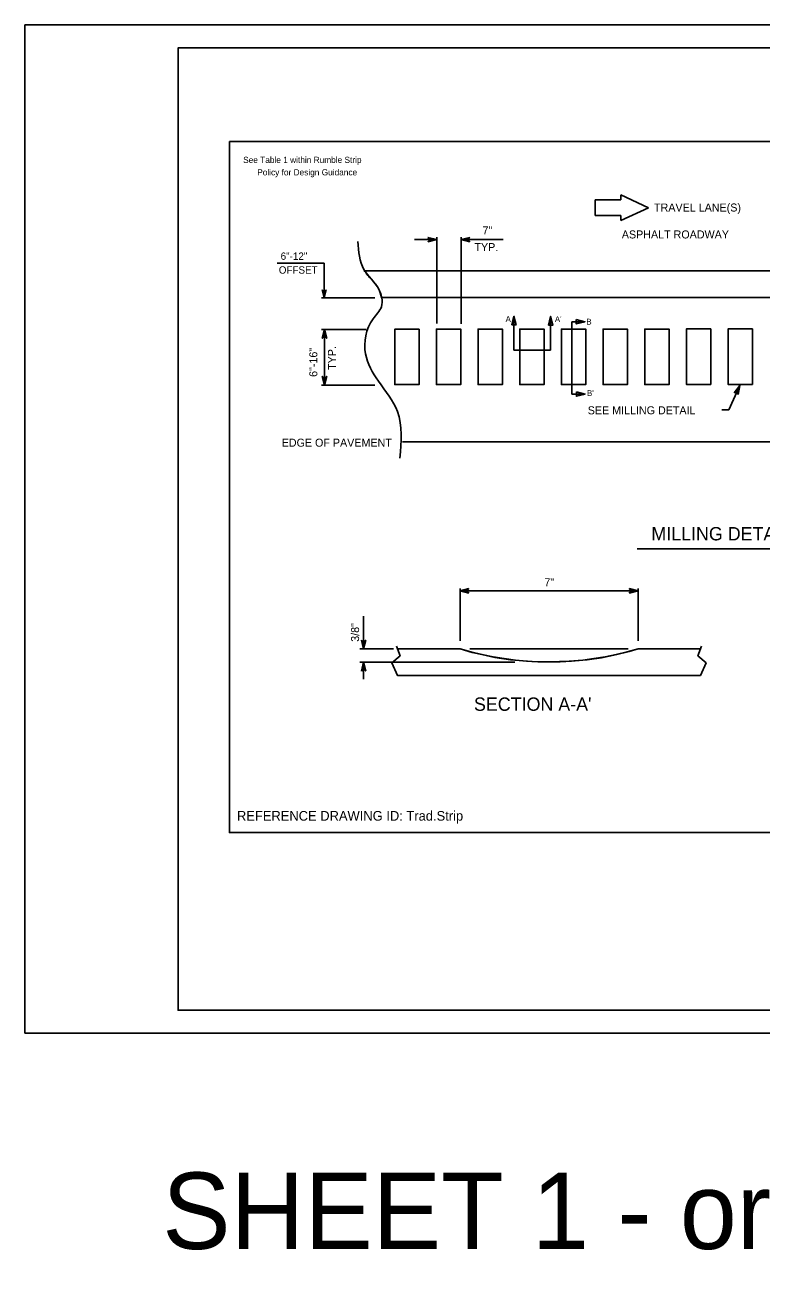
# Model space of a CAD drawing. Extents: x 1994737 to 2001433, y 527447 to 529360.
# Drawn here: x 1994737 to 1995696, y 527488 to 529114 of the extents above; entities that cross this region are included whole.
import ezdxf

# ---------------------------------------------------------------- set-up
doc = ezdxf.new("R2010")
doc.units = 0
for name, color, linetype in [('Default', 7, 'Continuous'), ('GSBWFILL', 7, 'Continuous'), ('Old_Level_33', 7, 'Continuous'), ('Prop Sign E Yield Sign Ahead CELL', 7, 'Continuous'), ('Prop Support Two', 7, 'Continuous')]:
    doc.layers.add(name, color=color, linetype=linetype)

# ---------------------------------------------------------------- blocks, each defined once
blk = doc.blocks.new('DTF')
at = {"layer": 'Default'}
for p, q in [((-10.33475, 4.8755), (-10.33625, 2.90475)), ((0, 0), (-10.33475, 4.8755)), ((-19.936, 2.9115), (-19.9395, -2.8845)), ((-10.33625, 2.90475), (-19.936, 2.9115)), ((-10.34125, -4.8615), (0, 0)), ((-19.9395, -2.8845), (-10.3405, -2.891)), ((-10.3405, -2.891), (-10.34125, -4.8615))]:
    blk.add_line(p, q, dxfattribs=at)
blk = doc.blocks.new('TERM2')
at = {"layer": 'Default'}
for p, q in [((-6.25, 1.563), (0, 0)), ((-4.687, 0), (-6.25, 1.563)), ((0, 0), (-6.25, -1.563)), ((-6.25, -1.563), (-4.687, 0))]:
    blk.add_line(p, q, dxfattribs=at)

msp = doc.modelspace()

# ---------------------------------------------------------------- linework, layer by layer
at = {"layer": 'Default'}
for p, q in [((1995273.6, 528834.2), (1995244.7, 528834.2)), ((1995273.6, 528724.6), (1995273.6, 528837.5)), ((1995305.3, 528724.5), (1995305.3, 528837.5)), ((1995305.3, 528834.2), (1995360.2, 528834.2)), ((1995065.8, 528803.5), (1995127, 528803.5)), ((1995127, 528758.1), (1995127, 528803.5)), ((1995178.8, 528793.5), (1995986.2, 528793.5)), ((1995985.9, 528793.5), (1995179.6, 528793.5)), ((1995193, 528758.1), (1995123.4, 528758.1)), ((1995201.2, 528758.5), (1995964.5, 528758.5)), ((1995201.7, 528758.5), (1995963.8, 528758.5)), ((1995374.1, 528689.9), (1995374.1, 528734.3)), ((1995422, 528689.9), (1995422, 528734.1)), ((1995449.4, 528727.1), (1995449.4, 528632.7)), ((1995449.6, 528727.1), (1995466, 528727.1)), ((1995181.6, 528717), (1995123.3, 528717)), ((1995127.3, 528717), (1995127.3, 528644.6)), ((1995374.1, 528689.9), (1995422, 528689.9)), ((1995193, 528644.6), (1995123.3, 528644.6)), ((1995668.3, 528643.9), (1995654, 528612.1)), ((1995449.4, 528632.7), (1995466.1, 528632.7)), ((1995654.1, 528612.1), (1995645.2, 528612.1)), ((1995228.8, 528570.4), (1995936.7, 528570.4)), ((1995534.7, 528431.2), (1995796.9, 528431.2)), ((1995303.9, 528311.1), (1995303.9, 528379.5)), ((1995535.8, 528311.1), (1995535.8, 528379.5)), ((1995303.9, 528376.3), (1995535.8, 528376.3)), ((1995178.3, 528300.5), (1995178.3, 528343.3)), ((1995217.4, 528300.5), (1995173.2, 528300.5)), ((1995221.2, 528304), (1995225.8, 528291.6)), ((1995222.5, 528300.5), (1995303.9, 528300.5)), ((1995316.7, 528300.5), (1995523, 528300.5)), ((1995535.8, 528300.5), (1995617.2, 528300.5)), ((1995618.5, 528304), (1995613.9, 528291.6)), ((1995375.5, 528283.1), (1995173.2, 528283.1)), ((1995178.3, 528283.1), (1995178.3, 528261.1)), ((1995225.8, 528291.6), (1995215.2, 528282.3)), ((1995215.2, 528282.3), (1995222.5, 528265.7)), ((1995613.9, 528291.6), (1995624.5, 528282.3)), ((1995624.5, 528282.3), (1995617.2, 528265.7)), ((1995222.5, 528265.7), (1995617.2, 528265.7))]:
    msp.add_line(p, q, dxfattribs=at)
for points in [[(1995003.5, 528962), (1996421.2, 528962), (1996421.2, 528061), (1995003.5, 528061)], [(1995371.3, 528722.9), (1995374.1, 528734.3), (1995377, 528722.9)], [(1995419.2, 528722.7), (1995422, 528734.1), (1995424.9, 528722.7)], [(1995455.3, 528729.9), (1995466.7, 528727.1), (1995455.3, 528724.2)], [(1995218.9, 528717.4), (1995250.6, 528717.4), (1995250.6, 528645.1), (1995218.9, 528645.1)], [(1995250.6, 528645.1), (1995218.9, 528645.1), (1995218.9, 528717.4), (1995250.6, 528717.4)], [(1995273.2, 528717.6), (1995304.9, 528717.6), (1995304.9, 528645.2), (1995273.2, 528645.2)], [(1995273.2, 528717.6), (1995304.9, 528717.6), (1995304.9, 528645.2), (1995273.2, 528645.2)], [(1995327.5, 528717.6), (1995359.2, 528717.6), (1995359.2, 528645.2), (1995327.5, 528645.2)], [(1995327.5, 528645.2), (1995359.2, 528645.2), (1995359.2, 528717.6), (1995327.5, 528717.6)], [(1995381.8, 528717.6), (1995413.5, 528717.6), (1995413.5, 528645.2), (1995381.8, 528645.2)], [(1995381.8, 528717.6), (1995413.5, 528717.6), (1995413.5, 528645.2), (1995381.8, 528645.2)], [(1995436, 528717.5), (1995467.7, 528717.5), (1995467.7, 528645.1), (1995436, 528645.1)], [(1995436, 528645.1), (1995467.7, 528645.1), (1995467.7, 528717.5), (1995436, 528717.5)], [(1995490.3, 528717.5), (1995521.9, 528717.5), (1995521.9, 528645.1), (1995490.3, 528645.1)], [(1995490.3, 528717.5), (1995521.9, 528717.5), (1995521.9, 528645.1), (1995490.3, 528645.1)], [(1995544.6, 528717.5), (1995576.2, 528717.5), (1995576.2, 528645.1), (1995544.6, 528645.1)], [(1995544.6, 528717.5), (1995576.2, 528717.5), (1995576.2, 528645.1), (1995544.6, 528645.1)], [(1995598.9, 528717.7), (1995630.5, 528717.7), (1995630.5, 528645.3), (1995598.9, 528645.3)], [(1995598.9, 528717.7), (1995630.5, 528717.7), (1995630.5, 528645.3), (1995598.9, 528645.3)], [(1995653.1, 528717.7), (1995684.8, 528717.7), (1995684.8, 528645.3), (1995653.1, 528645.3)], [(1995653.1, 528717.7), (1995684.8, 528717.7), (1995684.8, 528645.3), (1995653.1, 528645.3)], [(1995455.5, 528635.6), (1995466.9, 528632.7), (1995455.5, 528629.9)], [(1995535.8, 528300.5), (1995617.2, 528300.5), (1995613.9, 528291.6), (1995624.5, 528282.3), (1995617.2, 528265.7), (1995222.5, 528265.7), (1995215.2, 528282.3), (1995225.8, 528291.6), (1995222.5, 528300.5), (1995303.9, 528300.5), (1995319.6, 528296), (1995332.5, 528293.4), (1995349.3, 528289.5), (1995369.6, 528286.5), (1995397.6, 528283.9), (1995420.4, 528283.5), (1995446.3, 528284.4), (1995469.6, 528286.5), (1995488.1, 528289.1), (1995508.3, 528293.4), (1995524.3, 528297.3), (1995535.8, 528300.5)]]:
    msp.add_lwpolyline(points, close=True, dxfattribs=at)
for points in [[(1995218.9, 528645.1), (1995250.6, 528645.1), (1995250.6, 528717.4), (1995218.9, 528717.4), (1995218.9, 528645.1)], [(1995273.2, 528645.2), (1995304.9, 528645.2), (1995304.9, 528717.6), (1995273.2, 528717.6), (1995273.2, 528645.2)], [(1995327.5, 528645.2), (1995359.2, 528645.2), (1995359.2, 528717.6), (1995327.5, 528717.6), (1995327.5, 528645.2)], [(1995381.8, 528645.2), (1995413.5, 528645.2), (1995413.5, 528717.6), (1995381.8, 528717.6), (1995381.8, 528645.2)], [(1995436, 528645.1), (1995467.7, 528645.1), (1995467.7, 528717.5), (1995436, 528717.5), (1995436, 528645.1)], [(1995490.3, 528645.1), (1995521.9, 528645.1), (1995521.9, 528717.5), (1995490.3, 528717.5), (1995490.3, 528645.1)], [(1995544.6, 528645.1), (1995576.2, 528645.1), (1995576.2, 528717.5), (1995544.6, 528717.5), (1995544.6, 528645.1)], [(1995598.9, 528645.3), (1995630.5, 528645.3), (1995630.5, 528717.7), (1995598.9, 528717.7), (1995598.9, 528645.3)], [(1995653.1, 528645.3), (1995684.8, 528645.3), (1995684.8, 528717.7), (1995653.1, 528717.7), (1995653.1, 528645.3)]]:
    msp.add_lwpolyline(points, dxfattribs=at)
msp.add_arc((1995419.9, 528689.6), 406, 253.4, 286.5999, dxfattribs=at)
for points in [[(1995170.8, 528831.7), (1995178.8, 528795.2), (1995197.6, 528770.4), (1995201.5, 528746.6), (1995190.7, 528730.8), (1995180.8, 528685.2), (1995197.6, 528649.6), (1995222.3, 528609.9), (1995225.5, 528549.4)], [(1995179.6, 528793.5), (1995181.6, 528790.4), (1995183.8, 528787.4), (1995188.7, 528782), (1995193.6, 528776.5), (1995195.7, 528773.6), (1995197.6, 528770.4), (1995201.7, 528758.5)]]:
    msp.add_spline(points, degree=3, dxfattribs=at)
at = {"layer": 'GSBWFILL'}
for p, q in [((1996749.7, 529114.1), (1994737.1, 529114.1)), ((1994737.1, 529114.1), (1994737.1, 527799.4)), ((1994737.1, 527799.4), (1996749.7, 527799.4))]:
    msp.add_line(p, q, dxfattribs=at)
at = {"layer": 'Old_Level_33'}
msp.add_line((1994937.9, 529084.2), (1994937.9, 529084.2), dxfattribs=at)
at = {"layer": 'Prop Sign E Yield Sign Ahead CELL'}
msp.add_lwpolyline([(1996729.4, 529084.2), (1994936.7, 529084.2), (1994936.7, 527829.3), (1996729.4, 527829.3)], close=True, dxfattribs=at)
at = {"layer": 'Prop Support Two'}
msp.add_line((1994737.1, 527799.4), (1994737.1, 527799.4), dxfattribs=at)

# ---------------------------------------------------------------- block references
at = {"layer": 'Default', "xscale": 3.4793784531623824, "yscale": 3.4793784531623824}
msp.add_blockref('DTF', (1995549.3, 528875.8), dxfattribs=at)
at = {"layer": 'Default'}
for p, xscale, yscale, rotation in [((1995273.6, 528834.2), 1.8556685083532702, 1.8556685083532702, 2.7372046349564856e-11), ((1995305.3, 528834.2), 1.8556685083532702, 1.8556685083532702, -179.99999999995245), ((1995127, 528758.1), 1.7040114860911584, 1.7040114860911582, -89.99999999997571), ((1995127.3, 528717), 1.8556685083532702, 1.8556685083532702, 89.99999999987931), ((1995127.3, 528644.6), 1.8556685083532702, 1.8556685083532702, -90.0000000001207), ((1995668.3, 528643.9), 1.8556685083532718, 1.8556685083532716, 65.81937702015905), ((1995303.9, 528376.3), 1.8556685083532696, 1.85566850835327, 179.99984077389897), ((1995535.8, 528376.3), 1.8556685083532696, 1.85566850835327, -0.0001592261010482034), ((1995178.3, 528300.5), 1.855668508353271, 1.8556685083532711, -89.99968490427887), ((1995178.3, 528283.1), 1.8556685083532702, 1.8556685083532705, 89.99993359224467)]:
    msp.add_blockref('TERM2', p, dxfattribs=dict(at, xscale=xscale, yscale=yscale, rotation=rotation))

# ---------------------------------------------------------------- texts
for s, height, rotation, p in [('See Table 1 within Rumble Strip', 8.074, 360, (1995021.4, 528934.1)), ('Policy for Design Guidance', 8.074, 360, (1995039.7, 528917.9)), ('TRAVEL LANE(S)', 10.438, 360, (1995556.7, 528870.8)), ('7"', 10.44, 360, (1995333.2, 528841)), ('ASPHALT ROADWAY', 10.438, 360, (1995514.7, 528835.7)), ('6"-12"', 9.59, 360, (1995070.2, 528807.8)), ('TYP.', 10.44, 360, (1995322.7, 528819.2)), ('OFFSET', 9.59, 360, (1995067.8, 528789.8)), ('A', 7.61, 0, (1995363.3, 528726.9)), ("A'", 7.61, 0, (1995427.5, 528726.7)), ('B', 7.61, 0, (1995468.6, 528723.4)), ('6"-16"', 10.44, 90, (1995118, 528655.2)), ('TYP.', 10.44, 90, (1995142.3, 528664.3)), ("B'", 7.61, 0, (1995469.4, 528630.4)), ('SEE MILLING DETAIL', 10.438, 360, (1995470.3, 528606.4)), ('EDGE OF PAVEMENT', 10.438, 360, (1995071.6, 528564.2)), ('MILLING DETAIL:', 17.397, 0, (1995553.2, 528442)), ('7"', 10.44, 0, (1995413.8, 528382.2)), ('3/8"', 10.44, 90.0002, (1995172.4, 528309.8)), ("SECTION A-A'", 17.397, 0, (1995322.1, 528219.8)), ('REFERENCE DRAWING ID: Trad.Strip', 12.592, 0, (1995013.3, 528076.6)), ('SHEET 1 - original', 99.727, 0, (1994916, 527518.1))]:
    msp.add_text(s, height=height, rotation=rotation, dxfattribs=at).set_placement(p)

doc.saveas('drawing.dxf')
